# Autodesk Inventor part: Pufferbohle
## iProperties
Created: 2009-04
Part Number: Pufferbohle
Document SubType Name: Modeling
Designer: Hans-Jürgen Eicke
Author: Hans-Jürgen Eicke
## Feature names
1. Extrusion1
